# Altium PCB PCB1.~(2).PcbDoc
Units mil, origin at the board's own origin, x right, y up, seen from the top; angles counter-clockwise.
Board outline 1925 x 1945 mil, 2 copper layers (Top Layer, Bottom Layer); 29 components, 26 nets, 100 pads, 0 vias.
Unrouted connection lines stored in the file: 55.
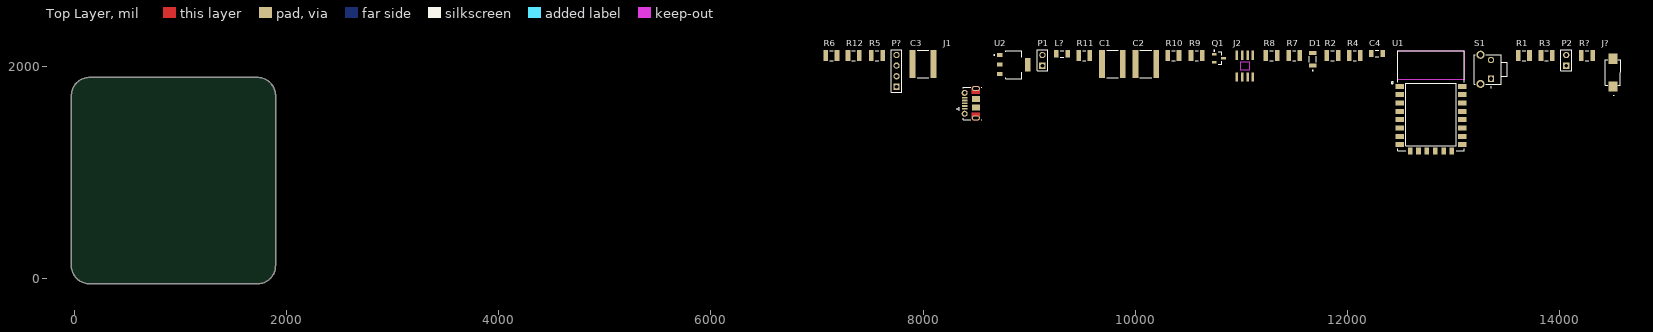
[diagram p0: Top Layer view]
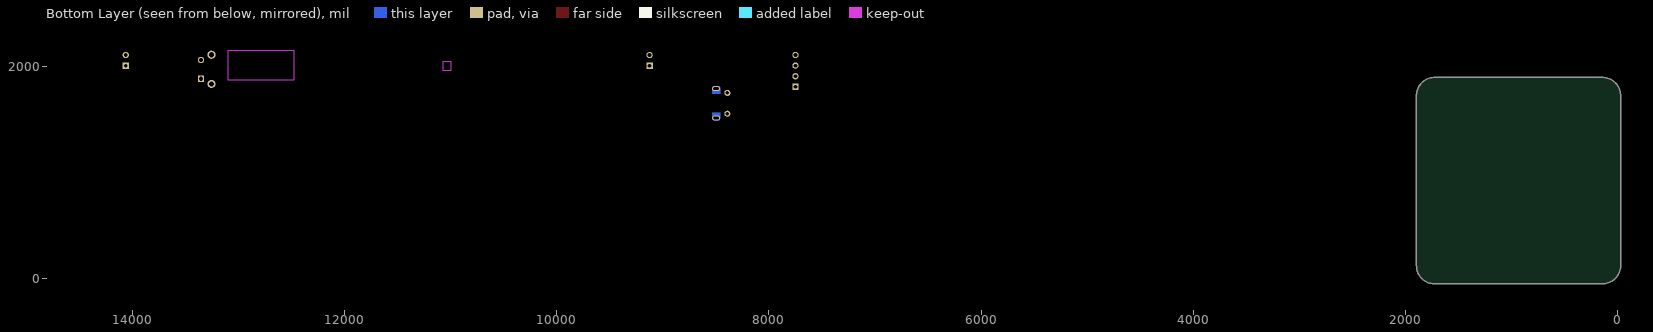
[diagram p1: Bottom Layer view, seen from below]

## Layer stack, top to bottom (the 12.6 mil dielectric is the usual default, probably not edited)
Top Solder: solder mask 0.4, Solder Resist, Dk 3.5
Top Layer: signal copper 1.4
Dielectric 1: dielectric 12.6, FR-4, Dk 4.8
Bottom Layer: signal copper 1.4
Bottom Solder: solder mask 0.4, Solder Resist, Dk 3.5

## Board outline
-31.26,118.33 -31.26,1723.33 cw(c138.74,1728.33) 133.74,1898.33 1718.74,1898.33 cw(c1723.74,1728.33) 1893.74,1733.33 1893.74,128.33 cw(c1723.74,123.33) 1728.74,-46.67 143.74,-46.67 cw(c138.74,123.33)

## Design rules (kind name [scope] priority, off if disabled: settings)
Clearance [All] p1: gap=10 ignorepadtopadclearanceinfootprint=FALSE except(0: Arc-Hole Track-Hole SMDPad-Hole THPad-Hole Via-Hole Fill-Hole Poly-Hole Region-Hole Text-Hole)
PolygonConnect [All] p1: connectstyle=Relief reliefconductorwidth=10 reliefentries=4 polygonreliefangle="90 Angle" airgapwidth=10
RoomDefinition Sheet1 [InComponentClass('Sheet1')] p1: confinementstyle=ConfineIn formatcopy=TRUE lockcomponents=FALSE outline 6093.74,-1991.67 13673.74,-1991.67 13673.74,-781.67 6093.74,-781.67
RoutingVias [All] p1: holewidth=28 width=50 viastyle="Through Hole" minholewidth=28 minwidth=50 maxholewidth=28 maxwidth=50
SolderMaskExpansion [All] p1: expansion=4 istentingtop=FALSE
Width [All] p1: maxlimit=10 minlimit=10 preferedwidth=10
30 further rules are at their usual default settings.

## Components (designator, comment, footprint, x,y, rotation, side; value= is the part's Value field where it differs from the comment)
C1 "" C2225 9785,2025 r0 top value=10uF
C2 "" C2225 10100,2025 r0 top value=10uF
C3 "" C2225 8000,2025 r0 top value=10uF
C4 "" C1206 12280,2125 r0 top value=100pF
D1 "LED" LEDC3216X120N 11675,2070 r90 top
J1 "1050170001" MOLEX_1050170001 8555,1655 r90 top
J2 "L9110" SO-08 11035,2005 r0 top
J? "SWITCH" PTS636SM25FSMTRLFS 14505,1945 r90 top
L? "Inductor" INDC3216 9310,2120 r0 top value=47uH
P1 "Battery" HDR1X2 9125,2010 r90 top
P2 "Battery" HDR1X2 14065,2010 r90 top
P? "Header 4" HDR1X4 7750,1810 r90 top
Q1 "PNP" SOT-23B_N 10790,2080 r0 top
R1 "" 14-1210 13665,2105 r0 top value=1K
R2 "" 14-1210 11860,2105 r0 top value=1K
R3 "" 14-1210 13880,2105 r0 top value=1K
R4 "" 14-1210 12070,2105 r0 top value=1K
R5 "" 14-1210 7565,2105 r0 top value=1K
R6 "" 14-1210 7135,2105 r0 top value=1K
R7 "" 14-1210 11500,2105 r0 top value=1K
R8 "" 14-1210 11285,2105 r0 top value=1K
R9 "" 14-1210 10580,2105 r0 top value=1K
R10 "" 14-1210 10360,2105 r0 top value=1K
R11 "" 14-1210 9520,2105 r0 top value=1K
R12 "" 14-1210 7345,2105 r0 top value=1K
R? "" 14-1210 14260,2105 r0 top value=1K
S1 "TL1105VF160Q" SW_TL1105VF160Q 13355,1975 r90 top
U1 "ESP8266-12E/ESP-12E" XCVR_ESP8266-12E/ESP-12E 12790,1540 r0 top
U2 "AMS1117" SOT229P700X180-4N 8855,2020 r0 top

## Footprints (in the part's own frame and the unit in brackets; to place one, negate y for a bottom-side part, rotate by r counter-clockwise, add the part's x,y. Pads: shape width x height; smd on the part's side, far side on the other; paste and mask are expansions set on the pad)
14-1210 [mm] "Chip Resistor, Body 3.2x2.5mm, IPC High Density"
  rect 1.1x2.6 smd: 1(-1.35,0) 2(1.35,0)
  silkscreen extent -0.4,-1.2 0.4,1.2, body extent -1.68,-1.32 1.68,1.32, height 0.9
C1206 [mm] "Chip Capacitor, Body 3.2x1.6mm, IPC High Density"
  rect 1.1x1.7 smd: 1(-1.35,0) 2(1.35,0)
  silkscreen extent -0.4,-0.75 0.4,0.75, body extent -1.7,-0.9 1.7,0.9, height 1.3
C2225 [mm] "Chip Capacitor, Body 5.7x6.4mm, IPC High Density"
  rect 1.4x6.7 smd: 1(-2.5,0) 2(2.5,0)
  silkscreen extent -1.4,-3.25 1.4,3.25, body extent -2.95,-3.4 2.95,3.4, height 1.4
HDR1X2 [mm] "Connector; Header; 2 Position"
  rect 1.5x1.5 hole 0.9: 1(0,0)
  round 1.5 hole 0.9: 2(2.54,0)
  silkscreen extent -1.27,-1.27 3.81,1.27
HDR1X4 [mm] "Connector; Header; 4 Position"
  rect 1.5x1.5 hole 0.9: 1(0,0)
  round 1.5 hole 0.9: 2(2.54,0) 3(5.08,0) 4(7.62,0)
  silkscreen extent -1.27,-1.27 8.89,1.27
INDC3216 [mm] "Chip Inductor, Body 3.2x1.6mm, IPC High Density"
  rect 1.1x1.8 smd: 1(-1.35,0) 2(1.35,0)
  silkscreen extent -0.4,-0.8 0.4,0.8, body extent -1.7,-0.9 1.7,0.9, height 0.55
LEDC3216X120N [mm]
  rect 1.01x1.73 smd: NEG(1.51,0) POS(-1.51,0)
  silkscreen extent -2.8,-0.8 0.68,0.8, body extent -1.6,-0.8 1.6,0.8, height 1.2
MOLEX_1050170001 [mm]
  rect 0.4x1.35 smd mask+0.064: 1(-1.3,4.125) 2(-0.65,4.125) 3(0,4.125) 4(0.65,4.125) 5(1.3,4.125)
  round 1.45 hole 0.85 mask+0.064: SH1(-2.5,4.15) SH2(2.5,4.15)
  oval 1.2x1.9 hole 0.6 slot 1.3 at 90 deg mask+0: SH3(-3.5,1.45) SH6(3.5,1.45)
  rect 1.5x1.9 smd mask+0.064: SH4(-1,1.45) SH5(1,1.45)
  Top Layer region: -2.3,0.5 -3.6,0.5 -3.626,0.501 -3.652,0.503 -3.678,0.506 -3.704,0.511 -3.729,0.517 -3.755,0.524 -3.779,0.533 -3.803,0.543 -3.827,0.554 -3.85,0.567 -3.872,0.581 -3.894,0.595 -3.915,0.611 -3.935,0.628 -3.954,0.646 -3.972,0.665 -3.989,0.685 -4.005,0.706 -4.019,0.728 -4.033,0.75 -4.046,0.773 -4.057,0.797 -4.067,0.821 -4.076,0.845 -4.083,0.871 -4.089,0.896 -4.094,0.922 -4.097,0.948 -4.099,0.974 -4.1,1 -4.1,1.9 -4.099,1.926 -4.097,1.952 -4.094,1.978 -4.089,2.004 -4.083,2.029 -4.076,2.055 -4.067,2.079 -4.057,2.103 -4.046,2.127 -4.033,2.15 -4.019,2.172 -4.005,2.194 -3.989,2.215 -3.972,2.235 -3.954,2.254 -3.935,2.272 -3.915,2.289 -3.894,2.305 -3.872,2.319 -3.85,2.333 -3.827,2.346 -3.803,2.357 -3.779,2.367 -3.755,2.376 -3.729,2.383 -3.704,2.389 -3.678,2.394 -3.652,2.397 -3.626,2.399 -3.6,2.4 -2.3,2.4
  Top Layer region: 3.626,2.399 3.652,2.397 3.678,2.394 3.704,2.389 3.729,2.383 3.755,2.376 3.779,2.367 3.803,2.357 3.827,2.346 3.85,2.333 3.872,2.319 3.894,2.305 3.915,2.289 3.935,2.272 3.954,2.254 3.972,2.235 3.989,2.215 4.005,2.194 4.019,2.172 4.033,2.15 4.046,2.127 4.057,2.103 4.067,2.079 4.076,2.055 4.083,2.029 4.089,2.004 4.094,1.978 4.097,1.952 4.099,1.926 4.1,1.9 4.1,1 4.099,0.974 4.097,0.948 4.094,0.922 4.089,0.896 4.083,0.871 4.076,0.845 4.067,0.821 4.057,0.797 4.046,0.773 4.033,0.75 4.019,0.728 4.005,0.706 3.989,0.685 3.972,0.665 3.954,0.646 3.935,0.628 3.915,0.611 3.894,0.595 3.872,0.581 3.85,0.567 3.827,0.554 3.803,0.543 3.779,0.533 3.755,0.524 3.729,0.517 3.704,0.511 3.678,0.506 3.652,0.503 3.626,0.501 3.6,0.5 2.3,0.5 2.3,2.4 3.6,2.4
  Bottom Layer region: 3.626,2.399 3.652,2.397 3.678,2.394 3.704,2.389 3.729,2.383 3.755,2.376 3.779,2.367 3.803,2.357 3.827,2.346 3.85,2.333 3.872,2.319 3.894,2.305 3.915,2.289 3.935,2.272 3.954,2.254 3.972,2.235 3.989,2.215 4.005,2.194 4.019,2.172 4.033,2.15 4.046,2.127 4.057,2.103 4.067,2.079 4.076,2.055 4.083,2.029 4.089,2.004 4.094,1.978 4.097,1.952 4.099,1.926 4.1,1.9 4.1,1 4.099,0.974 4.097,0.948 4.094,0.922 4.089,0.896 4.083,0.871 4.076,0.845 4.067,0.821 4.057,0.797 4.046,0.773 4.033,0.75 4.019,0.728 4.005,0.706 3.989,0.685 3.972,0.665 3.954,0.646 3.935,0.628 3.915,0.611 3.894,0.595 3.872,0.581 3.85,0.567 3.827,0.554 3.803,0.543 3.779,0.533 3.755,0.524 3.729,0.517 3.704,0.511 3.678,0.506 3.652,0.503 3.626,0.501 3.6,0.5 2.3,0.5 2.3,2.4 3.6,2.4
  Bottom Layer region: -2.3,0.5 -3.6,0.5 -3.626,0.501 -3.652,0.503 -3.678,0.506 -3.704,0.511 -3.729,0.517 -3.755,0.524 -3.779,0.533 -3.803,0.543 -3.827,0.554 -3.85,0.567 -3.872,0.581 -3.894,0.595 -3.915,0.611 -3.935,0.628 -3.954,0.646 -3.972,0.665 -3.989,0.685 -4.005,0.706 -4.019,0.728 -4.033,0.75 -4.046,0.773 -4.057,0.797 -4.067,0.821 -4.076,0.845 -4.083,0.871 -4.089,0.896 -4.094,0.922 -4.097,0.948 -4.099,0.974 -4.1,1 -4.1,1.9 -4.099,1.926 -4.097,1.952 -4.094,1.978 -4.089,2.004 -4.083,2.029 -4.076,2.055 -4.067,2.079 -4.057,2.103 -4.046,2.127 -4.033,2.15 -4.019,2.172 -4.005,2.194 -3.989,2.215 -3.972,2.235 -3.954,2.254 -3.935,2.272 -3.915,2.289 -3.894,2.305 -3.872,2.319 -3.85,2.333 -3.827,2.346 -3.803,2.357 -3.779,2.367 -3.755,2.376 -3.729,2.383 -3.704,2.389 -3.678,2.394 -3.652,2.397 -3.626,2.399 -3.6,2.4 -2.3,2.4
  silkscreen extent -3.9,0 3.9,6.15
PTS636SM25FSMTRLFS [mm]
  rect 2.4x2.1 smd: 1(-3.3,0) 2(3.3,0)
  silkscreen extent -5.6,-1.85 3.05,1.85, body extent -4.29,-2.8 4.29,0, height 1.85
SO-08 [mm]
  rect 0.6x2.2 smd: 1(-1.905,-2.6) 2(-0.635,-2.6) 3(0.635,-2.6) 4(1.905,-2.6) 5(1.905,2.6) 6(0.635,2.6) 7(-0.635,2.6) 8(-1.905,2.6)
  Keep-Out Layer region: 1,-1 -1,-1 -1,1 1,1
SOT229P700X180-4N [mm]
  rrect15% 1.31x0.93 smd: 1(-3.345,2.29) 2(-3.345,0) 3(-3.345,-2.29)
  rrect15% 1.31x3.24 smd: 4(3.345,0)
  silkscreen extent -4.8,-3.36 1.86,3.36, body extent -3.25,-3.5 3.25,3.5, height 1.8
SOT-23B_N [mm] "SOT23, 3-Leads, Body 2.9x1.3mm, Pitch 0.95mm, Lead Span 2.4mm, IPC Medium Density"
  rect 1.15x0.6 smd: 1(-1.125,0.95) 2(-1.125,-0.95) 3(1.125,0)
  silkscreen extent -1.25,-1.5 0.7,1.92, body extent -0.7,-1.5 0.7,1.5, height 1.14
SW_TL1105VF160Q [mm]
  rect 1.508x1.508 / inner round 1.508 / far side rect 1.508x1.508 hole 1 mask+0.102: 1(-2.25,0)
  round 1.508 hole 1 mask+0.102: 2(2.25,0)
  round 1.95 hole 1.3 mask+0.102: S1(-3.5,2.5) S2(3.5,2.5)
  silkscreen extent -4.35,-3.85 3.55,4, body extent -7.7,-4.64 3.3,3.21, height 4.2
XCVR_ESP8266-12E/ESP-12E [mm]
  rect 2x1.2 smd: 1(-7.5,7) 2(-7.5,5) 3(-7.5,3) 4(-7.5,1) 5(-7.5,-1) 6(-7.5,-3) 7(-7.5,-5) 8(-7.5,-7) 15(7.5,-7) 16(7.5,-5) 17(7.5,-3) 18(7.5,-1) 19(7.5,1) 20(7.5,3) 21(7.5,5) 22(7.5,7)
  rect 1.1x1.7 smd: 9(-5,-8.5) 10(-3,-8.5) 11(-1,-8.5) 12(1,-8.5) 13(3,-8.5) 14(5,-8.5)
  Keep-Out Layer region: 8,8.51 -8.009,8.51 -8.009,15.5 8,15.5
  Keep-Out Layer region: 8,8.51 -8.009,8.51 -8.009,15.5 8,15.5
  silkscreen extent -9.5,-8.5 8,15.5, body extent -8,-12 8,12, height 3

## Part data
C1 C2 C3: library part "Cap Pol3", "Polarized Capacitor (Surface Mount)"
C4: library part "Cap Semi", "Capacitor (Semiconductor SIM Model)"
D1: library part LHN974_RED_LED_1206, "2.6 V Red LED SMD", Package=None
J1: "USB - micro B USB 2.0 Receptacle Connector 5 Position Surface Mount, Right Angle; Through Hole", Package=None
J2: "Motor control driver chip", Package=Package
J?: library part PTS636_SM25F_SMTR_LFS, "Tactile Switch SPST-NO Top Actuated Surface Mount", Package=None
P1 P2: library part "Header 2", "Header, 2-Pin"
P?: "Header, 4-Pin"
Q1: "PNP Bipolar Transistor"
R1 R2 R3 R4 R5 R6 R7 R8 R9 R10 R11 R12 R?: library part Res3, "Resistor"
S1: "Tactile Switch, TL1105 Series, SPST-NO, 3.85mm Side Actuated, 0.05A, 12VDC, PC", Package=None
U1: "This WiFi module has a 32-bit MCU micro and clock speeds supporting 80 MHz or 160 MHz. Supports the RTOS and integrated Wi-Fi MAC/BB/RF/PA/LNA, and has an on-board antenna.", Package=None
U2: "1A LOW DROPOUT VOLTAGE REGULATOR SOT-223", Package="SOT-223 Seeed Technology"

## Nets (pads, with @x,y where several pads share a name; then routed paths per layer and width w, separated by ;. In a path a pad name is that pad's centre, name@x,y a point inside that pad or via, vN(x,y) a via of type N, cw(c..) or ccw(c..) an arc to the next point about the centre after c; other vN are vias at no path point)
+3.3: C3.1 P?.4 R9.2 R10.2 R11.2 R12.1 S1.1 U1.8 U2.2 U2.4
+5: J1.1 U2.3
ADC: R3.1 R4.1 U1.2
Battery: P2.1 Q1.3 R4.2
EN: R9.1 U1.3
GND: C1.2 C2.2 C3.2 C4.1 D1.NEG J1.5 J2.7 J2.8 J?.2 P2.2 P?.1 R3.2 R8.2 U1.15 U2.1
GPIO0: R11.1 U1.18
GPIO2: R10.1 U1.17
GPIO4: R7.1 U1.19
GPIO5: R2.2 U1.20
GPIO13: P?.3 R12.2 U1.7
GPIO14: R5.2 U1.5
GPIO15: R8.1 U1.16
GPIO16: R6.2 U1.4
L1: J2.1 R5.1
L2: J2.2 R6.1
NetC1_1: C1.1 J2.3 L?.1 Q1.1
NetC2_1: C2.1 J2.6 L?.2
NetD1_POS: D1.POS R7.2
NetJ2_4: J2.4 J2.5
NetJ?_1: J?.1 R?.2
NetR1_1: R1.1 R2.1 S1.2
ON/OFF: Q1.2 R1.2
RESET: C4.2 R?.1 U1.1
RX: P1.2 U1.21
TX: P1.1 U1.22
pads on no net: J1.2 J1.3 J1.4 J1.SH1 J1.SH2 J1.SH3 J1.SH4 J1.SH5 J1.SH6 P?.2 S1.S1 S1.S2 U1.6 U1.9 U1.10 U1.11 U1.12 U1.13 U1.14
